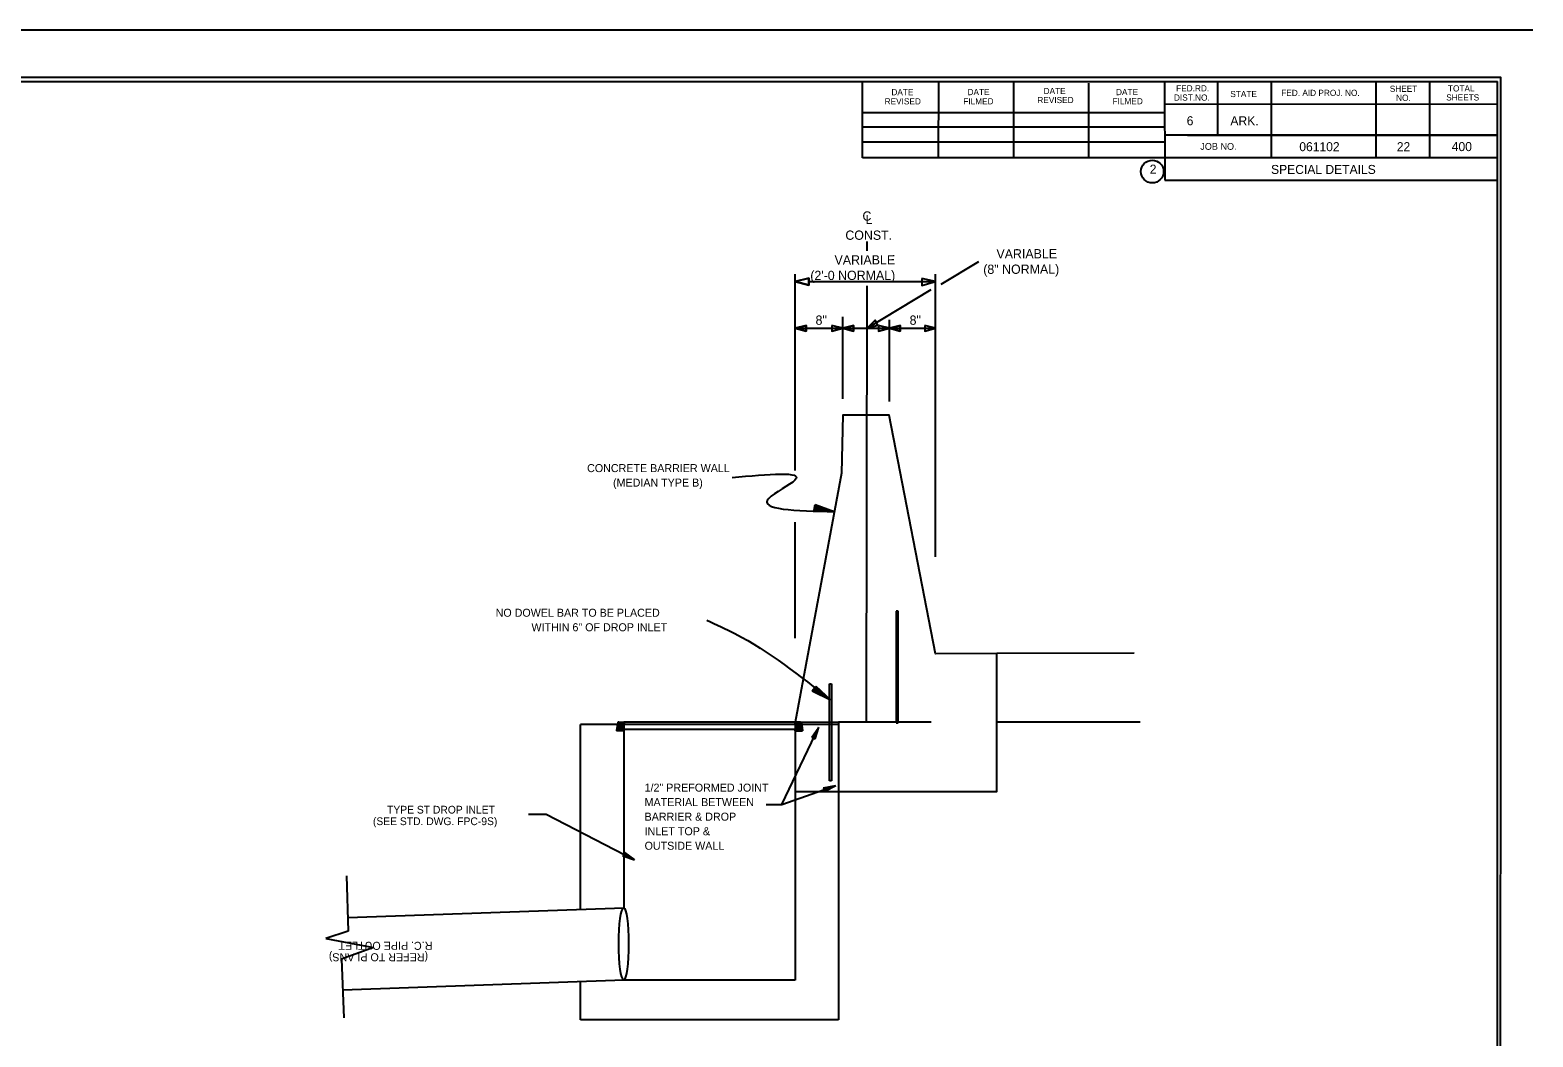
# Model space of a CAD drawing. Extents: x 714919 to 718439, y 1619644 to 1621844.
# Drawn here: x 716492 to 718439, y 1620539 to 1621844 of the extents above; entities that cross this region are included whole.
import ezdxf

# ---------------------------------------------------------------- set-up
doc = ezdxf.new("R2010")
doc.units = 0
for name, color, linetype in [('Level 1', 7, 'Continuous'), ('R_Annotation', 7, 'Continuous'), ('R_Border', 7, 'Continuous'), ('R_Centerline', 7, 'Continuous'), ('R_Dimension', 7, 'Continuous'), ('R_No Plot', 7, 'Continuous'), ('T_Drafting', 7, 'Continuous')]:
    doc.layers.add(name, color=color, linetype=linetype)

msp = doc.modelspace()

# ---------------------------------------------------------------- linework, layer by layer
at = {"layer": 'Level 1'}
msp.add_line((717605.1, 1621457.5), (717664.8, 1621457.5), dxfattribs=at)
for points in [[(717483.2, 1621518), (717500.7, 1621522.2), (717500.7, 1621513.3)], [(717483.2, 1621457.4), (717497.2, 1621460.8), (717497.2, 1621453.7)], [(717544.7, 1621457.4), (717558.8, 1621460.8), (717558.8, 1621453.7)], [(717605.1, 1621457.5), (717619.1, 1621460.8), (717619.1, 1621453.7)]]:
    msp.add_lwpolyline(points, close=True, dxfattribs=at)
for points in [[(717500.7, 1621513.3), (717500.7, 1621522.2), (717483.2, 1621518), (717500.7, 1621513.3)], [(717497.2, 1621453.7), (717497.2, 1621460.8), (717483.2, 1621457.4), (717497.2, 1621453.7)], [(717558.8, 1621453.7), (717558.8, 1621460.8), (717544.7, 1621457.4), (717558.8, 1621453.7)], [(717619.1, 1621453.7), (717619.1, 1621460.8), (717605.1, 1621457.5), (717619.1, 1621453.7)]]:
    msp.add_lwpolyline(points, dxfattribs=at)
at = {"layer": 'R_Annotation'}
for p, q in [((717507.5, 1621221.5), (717509.1, 1621229.1)), ((717507.5, 1621221.5), (717533.6, 1621219.9)), ((717507.6, 1621222), (717529.4, 1621220.8)), ((717507.8, 1621222.7), (717525.1, 1621221.7)), ((717507.9, 1621223.4), (717520.8, 1621222.6)), ((717508, 1621224), (717516.5, 1621223.5)), ((717508.2, 1621224.7), (717512.3, 1621224.4)), ((717508.4, 1621225.9), (717512.3, 1621224.4)), ((717508.5, 1621226.5), (717516.5, 1621223.5)), ((717508.7, 1621227.1), (717520.8, 1621222.6)), ((717508.8, 1621227.8), (717525.1, 1621221.7)), ((717508.9, 1621228.4), (717529.4, 1621220.8)), ((717509.1, 1621229.1), (717533.6, 1621219.9)), ((717505.3, 1620987.4), (717509.8, 1620993.8)), ((717505.3, 1620987.4), (717528.8, 1620975.8)), ((717505.6, 1620987.9), (717525.2, 1620978.2)), ((717506.1, 1620988.4), (717521.6, 1620980.8)), ((717506.4, 1620988.9), (717518.1, 1620983.2)), ((717506.8, 1620989.5), (717514.4, 1620985.7)), ((717507.2, 1620990.1), (717510.9, 1620988.3)), ((717507.9, 1620991), (717510.9, 1620988.3)), ((717508.2, 1620991.6), (717514.4, 1620985.7)), ((717508.7, 1620992.1), (717518.1, 1620983.2)), ((717509, 1620992.7), (717521.6, 1620980.8)), ((717509.4, 1620993.2), (717525.2, 1620978.2)), ((717509.8, 1620993.8), (717528.8, 1620975.8)), ((717465.6, 1620840.5), (717513.9, 1620940.7)), ((717504.8, 1620927.4), (717513.9, 1620940.7)), ((717504.8, 1620927.4), (717509.1, 1620925.3)), ((717505.2, 1620927.2), (717512.8, 1620938.3)), ((717505.5, 1620927), (717511.6, 1620935.8)), ((717505.9, 1620926.8), (717510.4, 1620933.4)), ((717506.3, 1620926.7), (717509.2, 1620931)), ((717506.6, 1620926.5), (717508.1, 1620928.6)), ((717507.3, 1620926.2), (717508.1, 1620928.6)), ((717507.7, 1620926), (717509.2, 1620931)), ((717508.1, 1620925.8), (717510.4, 1620933.4)), ((717508.4, 1620925.6), (717511.6, 1620935.8)), ((717508.8, 1620925.5), (717512.8, 1620938.3)), ((717509.1, 1620925.3), (717513.9, 1620940.7)), ((717465.6, 1620840.5), (717535.9, 1620865.1)), ((717520, 1620862.1), (717535.9, 1620865.1)), ((717520, 1620862.1), (717521.6, 1620857.5)), ((717520.1, 1620861.7), (717533.4, 1620864.2)), ((717520.3, 1620861.3), (717530.8, 1620863.3)), ((717520.4, 1620860.9), (717528.3, 1620862.4)), ((717520.6, 1620860.5), (717525.7, 1620861.5)), ((717520.7, 1620860.1), (717523.2, 1620860.6)), ((717520.9, 1620859.4), (717523.2, 1620860.6)), ((717521.1, 1620859.1), (717525.7, 1620861.5)), ((717521.2, 1620858.7), (717528.3, 1620862.4)), ((717521.3, 1620858.3), (717530.8, 1620863.3)), ((717521.5, 1620857.9), (717533.4, 1620864.2)), ((717521.6, 1620857.5), (717535.9, 1620865.1)), ((717137.7, 1620827.8), (717160.4, 1620827.8)), ((717160.4, 1620827.8), (717275.1, 1620768.8)), ((717445.4, 1620840.5), (717465.6, 1620840.5)), ((717261.9, 1620778.3), (717259.7, 1620774)), ((717259.7, 1620774), (717275.1, 1620768.8)), ((717259.9, 1620774.4), (717272.7, 1620770)), ((717260.1, 1620774.7), (717270.2, 1620771.3)), ((717260.3, 1620775.1), (717267.9, 1620772.5)), ((717260.5, 1620775.4), (717265.5, 1620773.8)), ((717260.7, 1620775.8), (717263.1, 1620775)), ((717261, 1620776.5), (717263.1, 1620775)), ((717261.2, 1620776.8), (717265.5, 1620773.8)), ((717261.4, 1620777.2), (717267.9, 1620772.5)), ((717261.6, 1620777.5), (717270.2, 1620771.3)), ((717261.8, 1620777.9), (717272.7, 1620770)), ((717261.9, 1620778.3), (717275.1, 1620768.8)), ((717261.5, 1620720), (717261.5, 1620721.6))]:
    msp.add_line(p, q, dxfattribs=at)
for points in [[(717401.3, 1621264), (717482.8, 1621260.6), (717448.9, 1621236.9), (717533.6, 1621219.9)], [(717368.7, 1621079.1), (717405.1, 1621061.7), (717528.8, 1620975.8)]]:
    msp.add_spline(points, degree=3, dxfattribs=at)
at = {"layer": 'R_Border'}
for p, q in [((718439, 1621843.8), (714919, 1621843.5)), ((715231.3, 1621777.1), (718393.1, 1621777.1)), ((717570.4, 1621678.3), (717570.5, 1621777.2)), ((717668.9, 1621678.3), (717669.1, 1621775.2)), ((717766.6, 1621678.2), (717766.6, 1621775.2)), ((717863.5, 1621678.3), (717863.5, 1621775.1)), ((717961.8, 1621777.1), (717962, 1621649.1)), ((718030.5, 1621777), (718030.4, 1621707.7)), ((718099.8, 1621777.1), (718099.8, 1621678.4)), ((718235.5, 1621777.2), (718235.5, 1621678.5)), ((718305, 1621777.3), (718305, 1621678.3)), ((718393.2, 1619722.5), (718393.1, 1621777.1)), ((718393, 1621747.5), (717962.1, 1621747.6)), ((718393.1, 1621747.9), (718393.1, 1621747.9)), ((717570.3, 1621736.9), (717961.9, 1621736.9)), ((717570.4, 1621718.3), (717961.9, 1621718.3)), ((718393.1, 1621707.7), (717962, 1621707.7)), ((717991.6, 1621707.7), (718393.1, 1621707.7)), ((717570.4, 1621678.3), (717570.4, 1621699)), ((717570.4, 1621699), (717962.1, 1621699)), ((718393.1, 1621678.3), (717570.4, 1621678.3)), ((717962, 1621649.1), (718393.1, 1621649.2))]:
    msp.add_line(p, q, dxfattribs=at)
msp.add_circle((717945.8, 1621660.4), 14.7, dxfattribs=at)
at = {"layer": 'R_Centerline'}
for p, q in [((717576.2, 1621557.7), (717576.2, 1621569.6)), ((717575.6, 1620947.1), (717576.2, 1621512.2))]:
    msp.add_line(p, q, dxfattribs=at)
at = {"layer": 'R_Dimension'}
for p, q in [((717672.1, 1621514.3), (717721.2, 1621543.7)), ((717483.2, 1621272.9), (717483.2, 1621527.5)), ((717500.7, 1621517.8), (717664.8, 1621517.8)), ((717664.8, 1621161.3), (717664.8, 1621527.5)), ((717576.2, 1621457.4), (717659.5, 1621507.4)), ((717544.8, 1621366), (717544.8, 1621472)), ((717483.2, 1621457.4), (717544.7, 1621457.4)), ((717544.7, 1621457.4), (717605.1, 1621457.4)), ((717605.1, 1621362.7), (717605.1, 1621468.5)), ((717483.2, 1621055.9), (717483.2, 1621206.3)), ((717483.2, 1620829.5), (717483.2, 1620795.3))]:
    msp.add_line(p, q, dxfattribs=at)
for points in [[(717500.7, 1621513.3), (717500.7, 1621522.2), (717483.2, 1621518), (717500.7, 1621513.3)], [(717497.2, 1621453.7), (717497.2, 1621460.8), (717483.2, 1621457.4), (717497.2, 1621453.7)], [(717558.8, 1621453.7), (717558.8, 1621460.8), (717544.7, 1621457.4), (717558.8, 1621453.7)], [(717619.1, 1621453.7), (717619.1, 1621460.8), (717605.1, 1621457.5), (717619.1, 1621453.7)]]:
    msp.add_lwpolyline(points, dxfattribs=at)
for points in [[(717647.3, 1621521.9), (717647.3, 1621513), (717664.8, 1621517.8)], [(717530.7, 1621460.8), (717530.7, 1621453.7), (717544.8, 1621457.4)], [(717590.1, 1621461.6), (717586.6, 1621467.7), (717576.2, 1621457.4)], [(717591, 1621460.8), (717591, 1621453.7), (717605.1, 1621457.4)], [(717651.3, 1621460.8), (717651.3, 1621453.7), (717664.8, 1621457.5)]]:
    msp.add_lwpolyline(points, close=True, dxfattribs=at)
at = {"layer": 'R_No Plot'}
msp.add_lwpolyline([(715227.2, 1619717.3), (718397.1, 1619717.4), (718397.2, 1621782.5), (715227.1, 1621782.3)], close=True, dxfattribs=at)
at = {"layer": 'T_Drafting'}
for p, q in [((717616.5, 1621090.9), (717613.9, 1621090.9)), ((717613.9, 1621090.9), (717613.9, 1620946.2)), ((717616.5, 1620946.2), (717616.5, 1621090.9)), ((717922.2, 1621036.6), (717744.2, 1621036.1)), ((717527.7, 1620870.8), (717527.7, 1620996.5)), ((717527.7, 1620996.5), (717530.3, 1620996.5)), ((717530.3, 1620996.5), (717530.3, 1620870.8)), ((717253.3, 1620947.1), (717251.5, 1620935.6)), ((717252.7, 1620943.1), (717254.8, 1620945.3)), ((717253.1, 1620946), (717254.2, 1620947.1)), ((717254.8, 1620947.1), (717253.3, 1620947.1)), ((717254.8, 1620937.8), (717254.8, 1620947.1)), ((717255, 1620947.2), (717261.3, 1620947.2)), ((717255, 1620937.8), (717255, 1620947.2)), ((717260, 1620939.8), (717255, 1620944.8)), ((717260.6, 1620941.9), (717255.3, 1620947.2)), ((717261.1, 1620944.1), (717258, 1620947.2)), ((717259.5, 1620937.8), (717261.8, 1620946.7)), ((717261.7, 1620946.1), (717260.6, 1620947.2)), ((717483.2, 1620947.1), (717261.3, 1620947.2)), ((717483.2, 1620947.1), (717302, 1620947.1)), ((717481.6, 1620947.1), (717417.3, 1620947.1)), ((717485, 1620937.8), (717482.6, 1620946.6)), ((717482.8, 1620946.1), (717483.8, 1620947.1)), ((717483.2, 1620947.1), (717539.4, 1620947.4)), ((717489.8, 1620947.1), (717483.2, 1620947.1)), ((717483.3, 1620944), (717486.4, 1620947.1)), ((717483.9, 1620941.8), (717489.2, 1620947.1)), ((717484.5, 1620939.8), (717489.5, 1620944.8)), ((717489.4, 1620937.8), (717489.8, 1620947.1)), ((717489.5, 1620937.8), (717489.5, 1620947.2)), ((717489.5, 1620947.2), (717491.1, 1620947.2)), ((717491.6, 1620943.1), (717489.7, 1620945)), ((717491.3, 1620946.1), (717490.2, 1620947.2)), ((717491.1, 1620947.2), (717492.7, 1620935.6)), ((717539.4, 1620947.5), (717659.1, 1620947.5)), ((717539.4, 1620947.4), (717539.4, 1620703.5)), ((717613.9, 1620946.2), (717616.5, 1620946.2)), ((717930.3, 1620947.1), (717744.2, 1620947.1)), ((717234.9, 1620944), (717205.1, 1620944)), ((717205.1, 1620704.1), (717205.1, 1620944)), ((717483.6, 1620944), (717234.9, 1620944)), ((717261.5, 1620935.6), (717251.5, 1620935.6)), ((717251.8, 1620937.2), (717254.8, 1620940.2)), ((717252.2, 1620940.1), (717254.8, 1620942.8)), ((717252.8, 1620935.6), (717255, 1620937.8)), ((717261.5, 1620937.8), (717254.8, 1620937.8)), ((717259.3, 1620937.8), (717255, 1620942.2)), ((717256.6, 1620937.8), (717255, 1620939.5)), ((717255, 1620937.8), (717259.5, 1620937.8)), ((717255.4, 1620935.6), (717257.5, 1620937.8)), ((717257.9, 1620935.6), (717260.1, 1620937.8)), ((717260.4, 1620935.6), (717261.5, 1620936.6)), ((717261.5, 1620706.1), (717261.5, 1620944)), ((717261.5, 1620935.6), (717261.5, 1620937.8)), ((717261.5, 1620937.8), (717489.4, 1620937.8)), ((717482.9, 1620935.6), (717482.9, 1620937.8)), ((717482.9, 1620937.8), (717489.5, 1620937.8)), ((717483.8, 1620935.6), (717482.9, 1620936.6)), ((717482.9, 1620935.6), (717492.7, 1620935.6)), ((717483.2, 1620935.6), (717483.2, 1620934.1)), ((717483.2, 1620934.1), (717483.2, 1620612.9)), ((717539.4, 1620944), (717483.6, 1620944)), ((717486.4, 1620935.6), (717484.3, 1620937.8)), ((717485.1, 1620937.8), (717489.5, 1620942.1)), ((717488.9, 1620935.6), (717486.8, 1620937.8)), ((717487.8, 1620937.8), (717489.5, 1620939.5)), ((717492.5, 1620937.2), (717489.5, 1620940.2)), ((717491.5, 1620935.6), (717489.5, 1620937.7)), ((717492.1, 1620940.1), (717489.6, 1620942.6)), ((717539.4, 1620944), (717491.5, 1620944)), ((717539.4, 1620944), (717539.4, 1620857.1)), ((717530.3, 1620870.8), (717527.7, 1620870.8)), ((716901.6, 1620748), (716903.8, 1620676.4)), ((717261.5, 1620706.1), (716903.3, 1620693.3)), ((717539.4, 1620703.5), (717539.4, 1620561.2)), ((716903.8, 1620676.4), (716874.9, 1620666.7)), ((716874.9, 1620666.7), (716936.9, 1620655)), ((716936.9, 1620655), (716895.2, 1620640)), ((716895.2, 1620640), (716898.4, 1620564)), ((717261.5, 1620612.9), (716896.9, 1620599.9)), ((717205.1, 1620561.2), (717205.1, 1620610.9)), ((717483.2, 1620612.9), (717261.5, 1620612.9)), ((717539.4, 1620561.2), (717205.1, 1620561.2))]:
    msp.add_line(p, q, dxfattribs=at)
for points in [[(717539.4, 1620857.1), (717744.2, 1620857.1), (717744.2, 1621036.1), (717664.8, 1621035.6), (717605, 1621344.9), (717544.8, 1621344.8), (717543.1, 1621269.6), (717483.2, 1620947.1)], [(717483.2, 1620947.1), (717483.2, 1620857.5)], [(717483.2, 1620857.1), (717539.4, 1620857.1)]]:
    msp.add_lwpolyline(points, dxfattribs=at)
for centre, radius, start, end in [((717261.4, 1620946.7), 0.47, 348.6901, 90), ((717483.1, 1620946.6), 0.47, 90, 191.3099), ((717254.8, 1620937.7), 0.452, 0, 90), ((717489.4, 1620937.7), 0.452, 90, 180)]:
    msp.add_arc(centre, radius, start, end, dxfattribs=at)
msp.add_ellipse((717260.9, 1620659.9), major_axis=(0, -46.3), ratio=0.137917, dxfattribs=at)

# ---------------------------------------------------------------- texts
at = {"layer": 'R_Annotation'}
for s, rotation, p in [('CONCRETE BARRIER WALL', 360, (717213.5, 1621271)), ('(MEDIAN TYPE B)', 360, (717247.1, 1621252.2)), ('R.C. PIPE OUTLET', 180, (717013.1, 1620662.4)), ('(REFER TO PLANS)', 180, (717007.5, 1620647.6))]:
    msp.add_text(s, height=10.367, rotation=rotation, dxfattribs=at).set_placement(p)
for s, height, p in [('NO DOWEL BAR TO BE PLACED', 10.367, (717095, 1621083.6)), ('WITHIN 6" OF DROP INLET', 10.367, (717141.4, 1621064.8)), ('1/2" PREFORMED JOINT', 10.367, (717288, 1620857)), ('MATERIAL BETWEEN', 10.367, (717288, 1620838.2)), ('TYPE ST DROP INLET', 9.999, (716954.3, 1620828.6)), ('BARRIER & DROP', 10.367, (717288, 1620819.4)), ('(SEE STD. DWG. FPC-9S)', 9.999, (716936, 1620813.6)), ('INLET TOP &', 10.367, (717288, 1620800.5)), ('OUTSIDE WALL', 10.367, (717288, 1620781.7))]:
    msp.add_text(s, height=height, dxfattribs=at).set_placement(p)
at = {"layer": 'R_Border'}
for s, height, rotation, p in [('DATE', 8, 0.0017, (717607.8, 1621759.3)), ('DATE', 8, 0.0017, (717706.4, 1621759.4)), ('DATE', 8, 0.0017, (717805, 1621760.8)), ('DATE', 8, 0.0017, (717898.8, 1621759.4)), ('FED.RD.', 8, 0.0017, (717976.7, 1621764.3)), ('STATE', 8, 0.0017, (718046.9, 1621756.9)), ('FED. AID PROJ. NO.', 8, 0.0017, (718112.9, 1621758.4)), ('SHEET', 8, 0.0017, (718253.5, 1621763.7)), ('TOTAL', 8, 0.0017, (718328.9, 1621764.2)), ('REVISED', 8, 0.0017, (717599, 1621747.4)), ('FILMED', 8, 0.0017, (717700.9, 1621747.5)), ('REVISED', 8, 0.0017, (717796.9, 1621749.1)), ('FILMED', 8, 0.0017, (717894.3, 1621747.6)), ('DIST.NO.', 8, 0.0017, (717973.9, 1621752.3)), ('NO.', 8, 0.0017, (718261.7, 1621752)), ('SHEETS', 8, 0.0017, (718326.6, 1621752.5)), ('6', 11.7, 0.0017, (717990.4, 1621720.4)), ('ARK.', 11.72, 0.0017, (718047, 1621720.3)), ('JOB NO.', 8.79, 0.0017, (718008, 1621688.6)), ('061102', 11.7, 0.0018, (718136.3, 1621686.8)), ('22', 11.7, 0.0018, (718262.6, 1621686.8)), ('400', 11.79, 0.0018, (718333.7, 1621686.9)), ('2', 11.7, 0.0017, (717942.5, 1621657.7)), ('SPECIAL DETAILS', 11.7, 0.0018, (718099.7, 1621657.3))]:
    msp.add_text(s, height=height, rotation=rotation, dxfattribs=at).set_placement(p)
at = {"layer": 'R_Dimension'}
for s, p in [('C', (717570.3, 1621596.8)), ('L', (717574.2, 1621592.3)), ('CONST.', (717548.1, 1621572))]:
    msp.add_text(s, height=12, dxfattribs=at).set_placement(p)
for s, height, p in [('VARIABLE', 12, (717534.1, 1621539.9)), ('VARIABLE', 12, (717743.9, 1621547.8)), ("(2'-0 NORMAL)", 11.999, (717502.7, 1621519.8)), ('(8" NORMAL)', 11.999, (717726.8, 1621527.8)), ('8"', 12, (717509.5, 1621461.9)), ('8"', 12, (717631.4, 1621461.9))]:
    msp.add_text(s, height=height, rotation=0.1435, dxfattribs=at).set_placement(p)

doc.saveas('drawing.dxf')
